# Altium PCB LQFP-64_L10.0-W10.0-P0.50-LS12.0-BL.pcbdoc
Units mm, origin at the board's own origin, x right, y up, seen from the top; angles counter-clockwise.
Board outline 26.2 x 26.2 mm, 2 copper layers (Top Layer, Bottom Layer); 1 components, 0 nets, 64 pads, 0 vias.
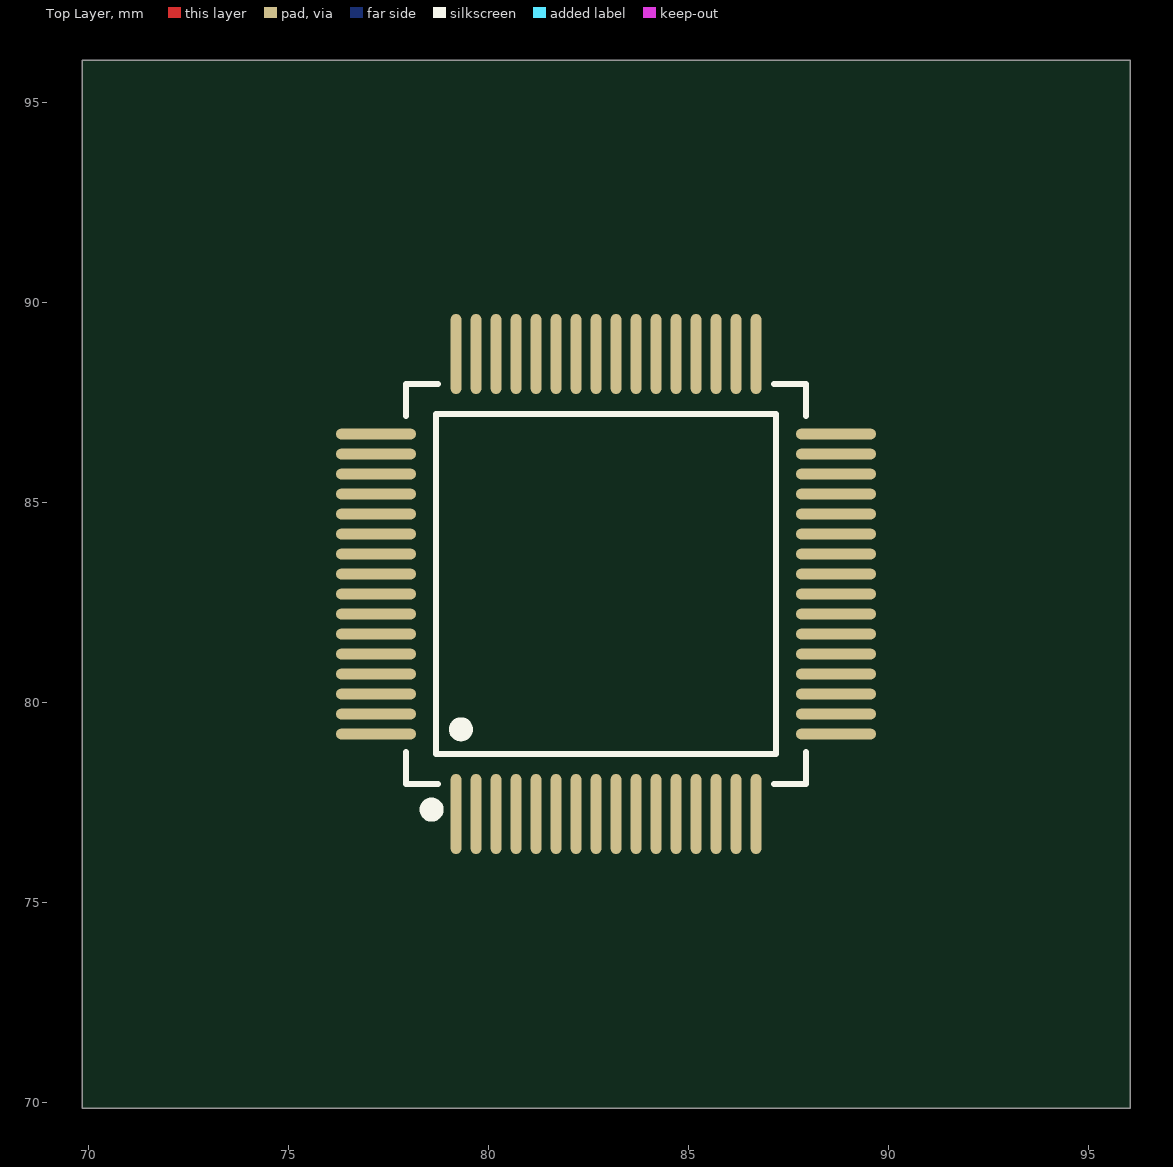
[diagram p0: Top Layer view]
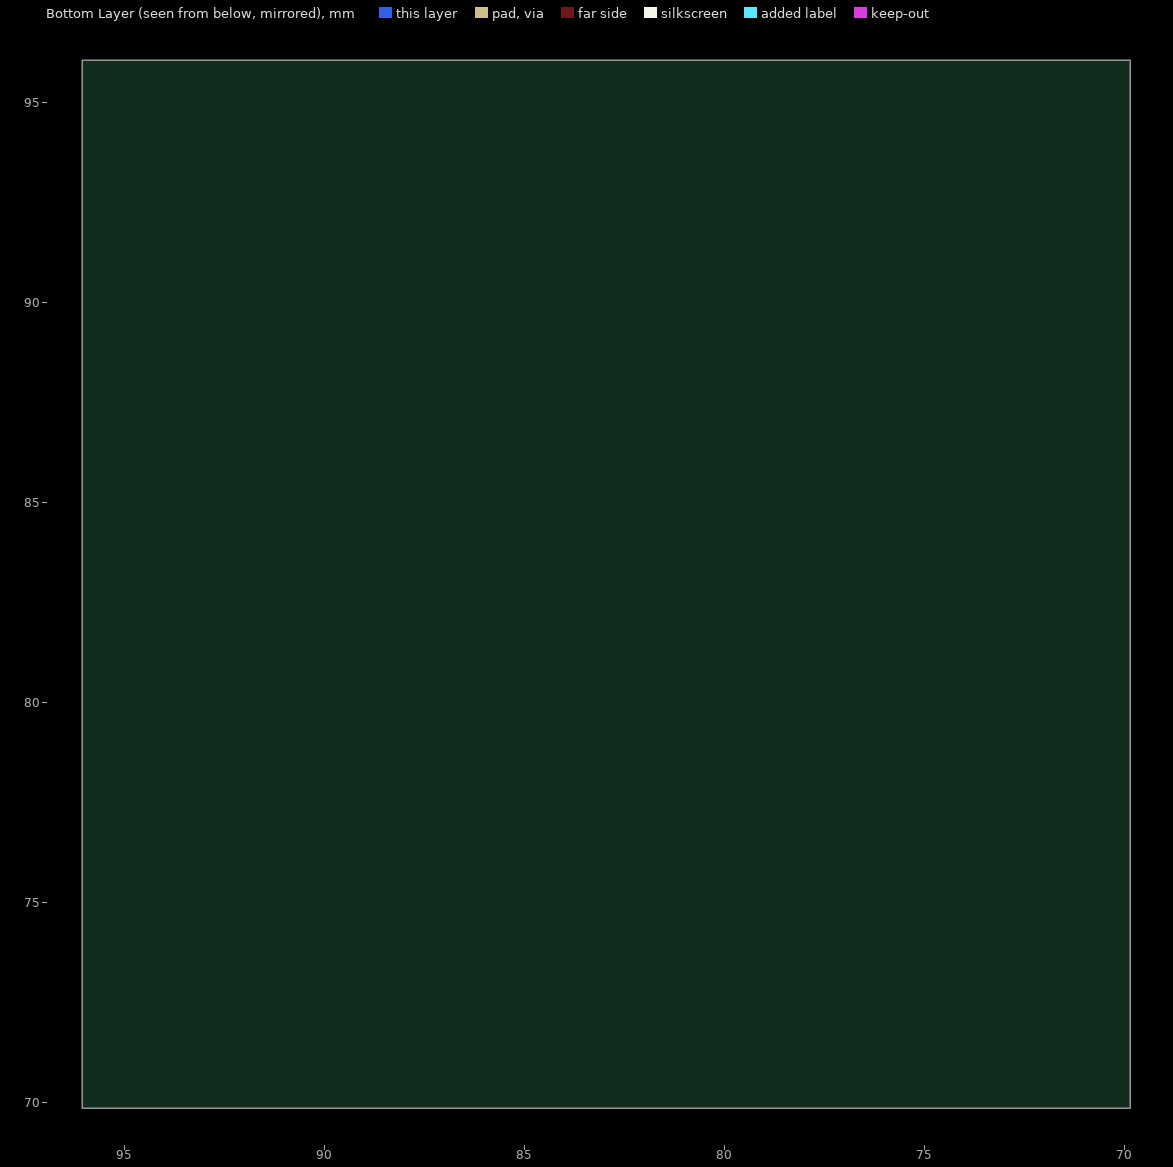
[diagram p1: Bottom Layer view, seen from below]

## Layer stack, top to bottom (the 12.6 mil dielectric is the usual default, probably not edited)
Top Layer: signal copper (thickness not stored)
Dielectric: dielectric 0.32, FR-4, Dk 4.8
Bottom Layer: signal copper (thickness not stored)

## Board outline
96.05,69.85 69.85,69.85 69.85,96.05 96.05,96.05

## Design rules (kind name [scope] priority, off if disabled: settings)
BoardOutlineClearance safeClearance [All] p0: genericclearance=0.254 ignorepadtopadclearanceinfootprint=FALSE except(0: Arc-SplitContinuation Track-SplitContinuation SMDPad-SplitContinuation THPad-SplitContinuation Via-SplitContinuation Fill-SplitContinuation Poly-SplitContinuation Region-SplitContinuation Text-SplitContinuation; 0.152: Track-CutoutEdge SMDPad-CutoutEdge THPad-CutoutEdge Via-CutoutEdge Fill-CutoutEdge Region-CutoutEdge; 0.3: Track-OutlineEdge SMDPad-OutlineEdge THPad-OutlineEdge Via-OutlineEdge Fill-OutlineEdge Region-OutlineEdge Poly-OutlineEdge Text-OutlineEdge)
Clearance safeClearance [All] p1: gap=0.178 ignorepadtopadclearanceinfootprint=FALSE except(0.152: Track-Track Track-SMDPad SMDPad-SMDPad Track-THPad SMDPad-THPad THPad-THPad Track-Via SMDPad-Via THPad-Via Via-Via Track-Fill SMDPad-Fill THPad-Fill Via-Fill Fill-Fill Track-Region SMDPad-Region THPad-Region Via-Region Fill-Region Region-Region Track-Poly SMDPad-Poly THPad-Poly Via-Poly Fill-Poly Region-Poly Poly-Poly Track-Text SMDPad-Text THPad-Text Via-Text Fill-Text Region-Text Poly-Text Text-Text; 0.175: Track-Hole SMDPad-Hole THPad-Hole Via-Hole Fill-Hole Region-Hole Poly-Hole Text-Hole Sheet-Hole; 0.3: Track-Sheet SMDPad-Sheet THPad-Sheet Via-Sheet Fill-Sheet Region-Sheet Poly-Sheet Text-Sheet)
DiffPairsRouting differentialPair [All] p1: maxuncoupledlength=10 minlimit=6 maxlimit=6 mostfreqgap=6 toplayer_minwidth=5 toplayer_prefwidth=10 toplayer_maxwidth=100 bottomlayer_minwidth=5 bottomlayer_prefwidth=10 bottomlayer_maxwidth=100
PasteMaskExpansion pasteMaskExpansion [All] p1: expansion=0
PlaneConnect innerPlane [All] p1: planeconnectstyle=Relief reliefexpansion=0.508 reliefentries=4 reliefconductorwidth=0.254 reliefairgap=0.254
PolygonConnect copperRegion [All] p1: connectstyle=Relief reliefentries=4 reliefconductorwidth=10 polygonreliefangle="90 Angle" airgapwidth=10
RoutingVias viaSize [All] p1: viastyle="Through Hole" holewidth=12.0078 minholewidth=11.811 maxholewidth=236.2204 width=24.0158 minwidth=19.685 maxwidth=393.7008
SolderMaskExpansion solderMaskExpansion [All] p1: useseparateexpansions=TRUE expansion=2 expansionbottom=2
Width trackWidth [All] p1: maxlimit=100 minlimit=5 preferedwidth=10

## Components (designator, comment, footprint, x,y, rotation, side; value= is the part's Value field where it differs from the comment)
? "LQFP-64_L10.0-W10.0-P0.50-LS12.0-BL" LQFP-64_L10.0-W10.0-P0.50-LS12.0-BL 82.95,82.95 r0 top

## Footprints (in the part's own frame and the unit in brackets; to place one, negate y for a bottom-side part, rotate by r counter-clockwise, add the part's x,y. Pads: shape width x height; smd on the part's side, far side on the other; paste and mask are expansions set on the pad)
LQFP-64_L10.0-W10.0-P0.50-LS12.0-BL [mm]
  oval 0.27x2 smd: 1(-3.75,-5.75) 2(-3.25,-5.75) 3(-2.75,-5.75) 4(-2.25,-5.75) 5(-1.75,-5.75) 6(-1.25,-5.75) 7(-0.75,-5.75) 8(-0.25,-5.75) 9(0.25,-5.75) 10(0.75,-5.75) 11(1.25,-5.75) 12(1.75,-5.75) 13(2.25,-5.75) 14(2.75,-5.75) 15(3.25,-5.75) 16(3.75,-5.75) 33(3.75,5.75) 34(3.25,5.75) 35(2.75,5.75) 36(2.25,5.75) 37(1.75,5.75) 38(1.25,5.75) 39(0.75,5.75) 40(0.25,5.75) 41(-0.25,5.75) 42(-0.75,5.75) 43(-1.25,5.75) 44(-1.75,5.75) 45(-2.25,5.75) 46(-2.75,5.75) 47(-3.25,5.75) 48(-3.75,5.75)
  oval 2x0.27 smd: 17(5.75,-3.75) 18(5.75,-3.25) 19(5.75,-2.75) 20(5.75,-2.25) 21(5.75,-1.75) 22(5.75,-1.25) 23(5.75,-0.75) 24(5.75,-0.25) 25(5.75,0.25) 26(5.75,0.75) 27(5.75,1.25) 28(5.75,1.75) 29(5.75,2.25) 30(5.75,2.75) 31(5.75,3.25) 32(5.75,3.75) 49(-5.75,3.75) 50(-5.75,3.25) 51(-5.75,2.75) 52(-5.75,2.25) 53(-5.75,1.75) 54(-5.75,1.25) 55(-5.75,0.75) 56(-5.75,0.25) 57(-5.75,-0.25) 58(-5.75,-0.75) 59(-5.75,-1.25) 60(-5.75,-1.75) 61(-5.75,-2.25) 62(-5.75,-2.75) 63(-5.75,-3.25) 64(-5.75,-3.75)
  silkscreen extent -5,-5.79 5,5

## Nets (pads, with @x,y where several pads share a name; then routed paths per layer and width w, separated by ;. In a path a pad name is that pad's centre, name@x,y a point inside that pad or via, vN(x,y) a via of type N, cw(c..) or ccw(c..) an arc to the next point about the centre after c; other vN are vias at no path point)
pads on no net: ?.1 ?.2 ?.3 ?.4 ?.5 ?.6 ?.7 ?.8 ?.9 ?.10 ?.11 ?.12 ?.13 ?.14 ?.15 ?.16 ?.17 ?.18 ?.19 ?.20 ?.21 ?.22 ?.23 ?.24 ?.25 ?.26 ?.27 ?.28 ?.29 ?.30 ?.31 ?.32 ?.33 ?.34 ?.35 ?.36 ?.37 ?.38 ?.39 ?.40 ?.41 ?.42 ?.43 ?.44 ?.45 ?.46 ?.47 ?.48 ?.49 ?.50 ?.51 ?.52 ?.53 ?.54 ?.55 ?.56 ?.57 ?.58 ?.59 ?.60 ?.61 ?.62 ?.63 ?.64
